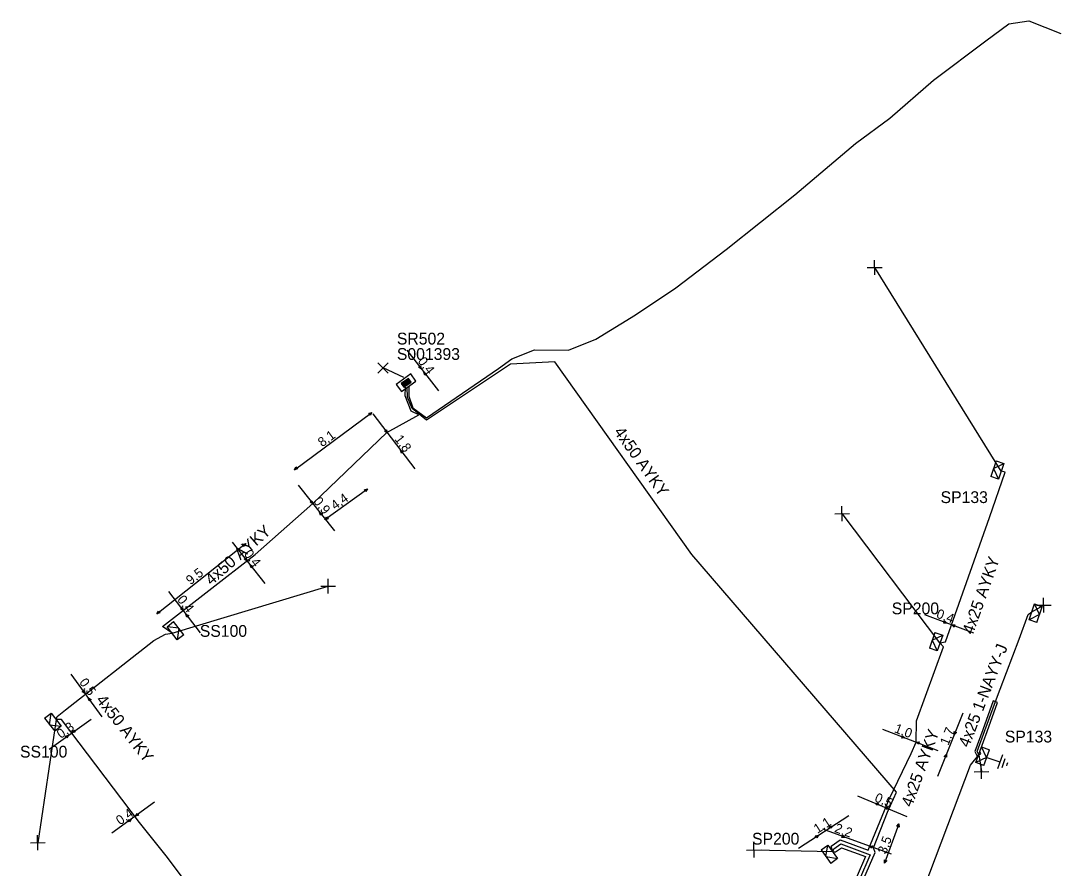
# Model space of a CAD drawing. Extents: x -762500 to -761285, y -1155006 to -1154135.
# Drawn here: x -761693.7 to -761606.3, y -1154578.8 to -1154507.3 of the extents above; entities that cross this region are included whole.
import ezdxf

# ---------------------------------------------------------------- set-up
doc = ezdxf.new("R2010")
doc.units = 0
for name, color, linetype in [('Vrstva 15', 7, 'Continuous'), ('Vrstva 20', 7, 'Continuous'), ('Vrstva 28', 7, 'Continuous'), ('Vrstva 29', 7, 'Continuous'), ('Vrstva 30', 7, 'Continuous'), ('Vrstva 31', 7, 'Continuous'), ('Vrstva 33', 7, 'Continuous'), ('Vrstva 34', 7, 'Continuous'), ('Vrstva 40', 7, 'Continuous'), ('Vrstva 5', 7, 'Continuous'), ('Vrstva 59', 7, 'Continuous'), ('Vrstva 6', 7, 'Continuous')]:
    doc.layers.add(name, color=color, linetype=linetype)

msp = doc.modelspace()

# ---------------------------------------------------------------- linework, layer by layer
at = {"layer": 'Vrstva 15'}
for points in [[(-761612.303, -1154569.415), (-761611.121, -1154569.822)], [(-761610.918, -1154569.231), (-761611.325, -1154570.412)], [(-761610.703, -1154569.559), (-761610.959, -1154570.304)], [(-761610.53, -1154570.025), (-761610.572, -1154570.146)], [(-761610.487, -1154569.899), (-761610.53, -1154570.025)]]:
    msp.add_lwpolyline(points, dxfattribs=at)
at = {"layer": 'Vrstva 20'}
msp.add_lwpolyline([(-761611.32, -1154564.8), (-761611.68, -1154564.67), (-761612.57, -1154567.12), (-761613.23, -1154568.95), (-761613.08, -1154569.29), (-761612.74, -1154569.13), (-761612.83, -1154568.93), (-761612.21, -1154567.25)], close=True, dxfattribs=at)
at = {"layer": 'Vrstva 28'}
for points in [[(-761660.844, -1154537.106), (-761662.057, -1154537.988)], [(-761660.403, -1154537.713), (-761660.844, -1154537.106)], [(-761662.057, -1154537.988), (-761661.616, -1154538.595)], [(-761661.034, -1154537.478), (-761661.636, -1154537.915)], [(-761661.636, -1154537.915), (-761661.414, -1154538.221)], [(-761661.616, -1154538.595), (-761660.403, -1154537.713)], [(-761661.044, -1154537.544), (-761661.57, -1154537.926)], [(-761661.57, -1154537.926), (-761661.403, -1154538.155)], [(-761661.055, -1154537.61), (-761661.504, -1154537.936)], [(-761661.504, -1154537.936), (-761661.393, -1154538.089)], [(-761661.065, -1154537.676), (-761661.438, -1154537.947)], [(-761661.438, -1154537.947), (-761661.382, -1154538.023)], [(-761661.414, -1154538.221), (-761660.812, -1154537.784)], [(-761661.403, -1154538.155), (-761660.878, -1154537.773)], [(-761661.393, -1154538.089), (-761660.943, -1154537.763)], [(-761661.382, -1154538.023), (-761661.009, -1154537.752)], [(-761661.071, -1154537.739), (-761661.376, -1154537.961)], [(-761661.009, -1154537.752), (-761661.065, -1154537.676)], [(-761660.943, -1154537.763), (-761661.055, -1154537.61)], [(-761660.878, -1154537.773), (-761661.044, -1154537.544)], [(-761660.812, -1154537.784), (-761661.034, -1154537.478)]]:
    msp.add_lwpolyline(points, dxfattribs=at)
at = {"layer": 'Vrstva 31'}
for points in [[(-761611.444, -1154544.418), (-761611.899, -1154545.741)], [(-761611.444, -1154544.418), (-761610.782, -1154544.645), (-761611.237, -1154545.969), (-761611.899, -1154545.741)], [(-761611.671, -1154545.079), (-761610.782, -1154544.645)], [(-761611.671, -1154545.079), (-761611.237, -1154545.969)], [(-761608.007, -1154558.053), (-761608.668, -1154557.825), (-761608.213, -1154556.501), (-761607.551, -1154556.729)], [(-761607.779, -1154557.391), (-761608.213, -1154556.501)], [(-761607.779, -1154557.391), (-761608.668, -1154557.825)], [(-761608.007, -1154558.053), (-761607.551, -1154556.729)], [(-761679.986, -1154559.092), (-761680.537, -1154559.523), (-761681.399, -1154558.42), (-761680.847, -1154557.989)], [(-761680.417, -1154558.541), (-761681.399, -1154558.42)], [(-761679.986, -1154559.092), (-761680.847, -1154557.989)], [(-761680.417, -1154558.541), (-761680.537, -1154559.523)], [(-761616.613, -1154558.897), (-761617.069, -1154560.221)], [(-761616.613, -1154558.897), (-761615.952, -1154559.125), (-761616.407, -1154560.449), (-761617.069, -1154560.221)], [(-761616.841, -1154559.559), (-761615.952, -1154559.125)], [(-761616.841, -1154559.559), (-761616.407, -1154560.449)], [(-761691.745, -1154566.127), (-761691.193, -1154565.696), (-761690.331, -1154566.799), (-761690.883, -1154567.23)], [(-761691.745, -1154566.127), (-761690.883, -1154567.23)], [(-761691.314, -1154566.679), (-761691.193, -1154565.696)], [(-761691.314, -1154566.679), (-761690.331, -1154566.799)], [(-761612.493, -1154570.11), (-761613.15, -1154569.87), (-761612.672, -1154568.555), (-761612.014, -1154568.794)], [(-761612.253, -1154569.452), (-761612.672, -1154568.555)], [(-761612.493, -1154570.11), (-761612.014, -1154568.794)], [(-761612.253, -1154569.452), (-761613.15, -1154569.87)], [(-761626.207, -1154577.226), (-761625.634, -1154576.825), (-761624.831, -1154577.972), (-761625.404, -1154578.373)], [(-761626.207, -1154577.226), (-761625.404, -1154578.373)], [(-761625.806, -1154577.8), (-761625.634, -1154576.825)], [(-761625.806, -1154577.8), (-761624.831, -1154577.972)]]:
    msp.add_lwpolyline(points, dxfattribs=at)
at = {"layer": 'Vrstva 34'}
for points in [[(-761621.679, -1154528.755), (-761621.701, -1154527.505)], [(-761622.315, -1154528.141), (-761621.065, -1154528.119)], [(-761663.622, -1154536.158), (-761662.738, -1154537.042)], [(-761663.622, -1154537.042), (-761662.738, -1154536.158)], [(-761624.429, -1154549.505), (-761624.451, -1154548.255)], [(-761625.065, -1154548.891), (-761623.815, -1154548.869)], [(-761667.799, -1154555.625), (-761667.821, -1154554.375)], [(-761668.435, -1154555.011), (-761667.185, -1154554.989)], [(-761608.045, -1154556.611), (-761606.795, -1154556.589)], [(-761607.409, -1154557.225), (-761607.431, -1154555.975)], [(-761613.305, -1154570.641), (-761612.055, -1154570.619)], [(-761612.669, -1154571.255), (-761612.691, -1154570.005)], [(-761692.935, -1154576.641), (-761691.685, -1154576.619)], [(-761692.299, -1154577.255), (-761692.321, -1154576.005)], [(-761631.869, -1154577.875), (-761631.891, -1154576.625)], [(-761632.505, -1154577.261), (-761631.255, -1154577.239)]]:
    msp.add_lwpolyline(points, dxfattribs=at)
at = {"layer": 'Vrstva 40'}
for points in [[(-761661.18, -1154535.09), (-761658.51, -1154538.54)], [(-761670.66, -1154545.18), (-761664.12, -1154540.35)], [(-761664.04, -1154540.47), (-761660.48, -1154545.11)], [(-761670.35, -1154546.49), (-761667.28, -1154550.32)], [(-761668.08, -1154549.39), (-761664.49, -1154546.79)], [(-761682.26, -1154557.33), (-761674.77, -1154551.41)], [(-761675.9, -1154551.29), (-761673.15, -1154554.77)], [(-761678.59, -1154558.94), (-761681.26, -1154555.46)], [(-761613.31, -1154558.96), (-761617.47, -1154557.41)], [(-761686.87, -1154566.03), (-761689.5, -1154562.42)], [(-761691.34, -1154568.73), (-761687.8, -1154566.21)], [(-761616.37, -1154571.01), (-761614.23, -1154565.68)], [(-761616.33, -1154568.87), (-761621.01, -1154567.08)], [(-761682.45, -1154573.22), (-761686.05, -1154575.83)], [(-761623.14, -1154572.67), (-761618.99, -1154574.43)], [(-761628.12, -1154577.08), (-761623.88, -1154574.33)], [(-761619.65, -1154575.04), (-761620.85, -1154578.35)], [(-761620.27, -1154577.61), (-761626.07, -1154575.5)]]:
    msp.add_lwpolyline(points, dxfattribs=at)
for points in [[(-761659.948, -1154536.672), (-761660.184, -1154536.541), (-761660.019, -1154536.412)], [(-761659.732, -1154536.958), (-761659.496, -1154537.09), (-761659.661, -1154537.218)], [(-761664.118, -1154540.349), (-761664.253, -1154540.582), (-761664.379, -1154540.415)], [(-761662.819, -1154542.062), (-761663.054, -1154541.931), (-761662.889, -1154541.802)], [(-761661.701, -1154543.518), (-761661.466, -1154543.649), (-761661.631, -1154543.778)], [(-761670.662, -1154545.181), (-761670.526, -1154544.948), (-761670.401, -1154545.115)], [(-761664.488, -1154546.788), (-761664.628, -1154547.019), (-761664.751, -1154546.85)], [(-761669.099, -1154548.052), (-761669.336, -1154547.925), (-761669.174, -1154547.793)], [(-761668.531, -1154548.758), (-761668.294, -1154548.885), (-761668.456, -1154549.017)], [(-761668.082, -1154549.391), (-761667.942, -1154549.161), (-761667.82, -1154549.33)], [(-761674.768, -1154551.408), (-761674.895, -1154551.646), (-761675.027, -1154551.483)], [(-761674.659, -1154552.862), (-761674.896, -1154552.735), (-761674.734, -1154552.603)], [(-761674.391, -1154553.198), (-761674.154, -1154553.325), (-761674.316, -1154553.457)], [(-761682.262, -1154557.331), (-761682.135, -1154557.093), (-761682.003, -1154557.256)], [(-761680.039, -1154557.052), (-761680.274, -1154556.921), (-761680.109, -1154556.792)], [(-761679.811, -1154557.348), (-761679.576, -1154557.479), (-761679.741, -1154557.608)], [(-761615.598, -1154558.111), (-761615.867, -1154558.125), (-761615.796, -1154557.928)], [(-761615.192, -1154558.259), (-761614.923, -1154558.246), (-761614.994, -1154558.443)], [(-761688.319, -1154564.042), (-761688.552, -1154563.907), (-761688.385, -1154563.781)], [(-761688.051, -1154564.408), (-761687.818, -1154564.544), (-761687.985, -1154564.669)], [(-761689.432, -1154567.371), (-761689.293, -1154567.141), (-761689.17, -1154567.31)], [(-761689.708, -1154567.569), (-761689.847, -1154567.799), (-761689.97, -1154567.63)], [(-761619.138, -1154567.791), (-761619.407, -1154567.804), (-761619.336, -1154567.608)], [(-761614.981, -1154567.533), (-761614.99, -1154567.263), (-761614.794, -1154567.338)], [(-761618.202, -1154568.149), (-761617.933, -1154568.136), (-761618.004, -1154568.332)], [(-761615.629, -1154569.158), (-761615.62, -1154569.428), (-761615.815, -1154569.353)], [(-761621.298, -1154573.451), (-761621.567, -1154573.45), (-761621.486, -1154573.258)], [(-761684.073, -1154574.392), (-761683.933, -1154574.161), (-761683.81, -1154574.33)], [(-761620.832, -1154573.649), (-761620.563, -1154573.65), (-761620.644, -1154573.842)], [(-761684.428, -1154574.649), (-761684.568, -1154574.88), (-761684.691, -1154574.711)], [(-761619.649, -1154575.038), (-761619.632, -1154575.307), (-761619.829, -1154575.239)], [(-761625.562, -1154575.421), (-761625.414, -1154575.195), (-761625.297, -1154575.369)], [(-761626.438, -1154575.989), (-761626.585, -1154576.215), (-761626.702, -1154576.042)], [(-761624.188, -1154576.181), (-761624.457, -1154576.199), (-761624.389, -1154576.001)], [(-761622.152, -1154576.919), (-761621.883, -1154576.901), (-761621.951, -1154577.099)], [(-761620.851, -1154578.353), (-761620.869, -1154578.083), (-761620.672, -1154578.151)]]:
    msp.add_lwpolyline(points, close=True, dxfattribs=at)
at = {"layer": 'Vrstva 5'}
for points in [[(-761661.01, -1154538.15), (-761660.99, -1154538.97), (-761660.65, -1154539.96), (-761659.51, -1154540.79), (-761653.43, -1154536.64), (-761652.32, -1154535.82), (-761650.39, -1154535.07), (-761647.54, -1154535.11), (-761645.23, -1154534.16), (-761641.87, -1154532.12), (-761638.47, -1154529.84), (-761634.23, -1154526.62), (-761628.42, -1154521.99), (-761623.3, -1154517.67), (-761620.4, -1154515.53), (-761616.72, -1154512.32), (-761612.32, -1154509), (-761610.36, -1154507.57), (-761608.67, -1154507.32), (-761605.97, -1154508.4)], [(-761622.04, -1154593.03), (-761622.16, -1154592.65), (-761626.67, -1154590.74), (-761622.6, -1154579.64), (-761621.66, -1154577.46), (-761621.79, -1154577.06), (-761620.62, -1154574.05), (-761619.85, -1154572.37), (-761637.13, -1154552.32), (-761648.69, -1154536.07), (-761652.41, -1154536.27), (-761659.5, -1154540.99), (-761660.72, -1154540.01), (-761661.12, -1154539.06), (-761661.14, -1154538.24)], [(-761675.5, -1154585.7), (-761681.49, -1154577.75), (-761683.72, -1154574.92), (-761690.32, -1154566.25), (-761690.76, -1154566.25), (-761690.67, -1154565.99), (-761689.96, -1154565.42), (-761682.51, -1154559.57), (-761681.53, -1154559.04), (-761680.97, -1154558.97), (-761681.79, -1154558.4), (-761673.98, -1154552.32), (-761669.1, -1154548.04), (-761662.87, -1154542.04), (-761660.16, -1154540.56), (-761660.81, -1154540.25), (-761661.32, -1154538.96), (-761661.29, -1154538.23)], [(-761616.18, -1154559.79), (-761615.72, -1154559.7), (-761612.01, -1154549.21), (-761610.67, -1154545.39), (-761611.01, -1154545.31)], [(-761612.91, -1154569.21), (-761613.03, -1154568.94), (-761612.39, -1154567.18), (-761611.5, -1154564.73), (-761611.11, -1154563.67), (-761609.49, -1154559.48), (-761608.74, -1154557.38), (-761608.44, -1154557.16)], [(-761625.23, -1154577.4), (-761625.36, -1154576.93), (-761624.59, -1154576.38), (-761622.24, -1154577.26), (-761620.48, -1154572.96), (-761618.62, -1154569.12), (-761618.2, -1154568.15), (-761618.16, -1154566.36), (-761615.88, -1154560.1), (-761616.18, -1154559.79)], [(-761621.99, -1154592.91), (-761621.89, -1154592.03), (-761613.6, -1154570.1), (-761612.91, -1154569.21)], [(-761625.23, -1154577.4), (-761625.15, -1154577.15), (-761624.54, -1154576.72), (-761622.06, -1154577.64), (-761622.18, -1154577.91), (-761622.88, -1154579.53), (-761625.16, -1154586.19), (-761627.06, -1154590.9), (-761622.47, -1154592.8), (-761622.09, -1154593.15)], [(-761625.23, -1154577.4), (-761624.99, -1154577.39), (-761624.5, -1154577.05), (-761622.46, -1154577.79), (-761623.16, -1154579.42), (-761625.44, -1154586.08), (-761627.34, -1154590.79), (-761629.49, -1154594.07), (-761630.52, -1154595.68), (-761634.83, -1154602.56), (-761636.8, -1154604.93), (-761639.28, -1154606.99), (-761645.39, -1154610.82), (-761648.2, -1154611.18), (-761650.88, -1154609.13), (-761652.37, -1154607.42), (-761653.76, -1154605.77), (-761656.21, -1154602.49), (-761657.87, -1154600.45), (-761657.72, -1154600.17)]]:
    msp.add_lwpolyline(points, dxfattribs=at)
at = {"layer": 'Vrstva 59'}
for points in [[(-761611.01, -1154545.31), (-761621.69, -1154528.13)], [(-761661.41, -1154537.41), (-761663.18, -1154536.6)], [(-761616.18, -1154559.79), (-761624.44, -1154548.88)], [(-761680.97, -1154558.97), (-761667.81, -1154555)], [(-761608.44, -1154557.16), (-761607.42, -1154556.6)], [(-761690.76, -1154566.25), (-761692.31, -1154576.63)], [(-761612.91, -1154569.21), (-761612.68, -1154570.63)], [(-761625.23, -1154577.4), (-761631.88, -1154577.25)]]:
    msp.add_lwpolyline(points, dxfattribs=at)

# ---------------------------------------------------------------- texts
at = {"layer": 'Vrstva 29'}
msp.add_text('S001393', height=0.9943, dxfattribs=at).set_placement((-761662.01, -1154535.92))
at = {"layer": 'Vrstva 30'}
msp.add_text('SR502', height=0.9943, dxfattribs=at).set_placement((-761662.01, -1154534.62))
at = {"layer": 'Vrstva 33'}
for s, p in [('SP133', (-761616.13, -1154547.99)), ('SP200', (-761620.25, -1154557.37)), ('SS100', (-761678.64, -1154559.27)), ('SP133', (-761610.71, -1154568.18)), ('SS100', (-761693.81, -1154569.45)), ('SP200', (-761632.04, -1154576.79))]:
    msp.add_text(s, height=0.9943, dxfattribs=at).set_placement(p)
at = {"layer": 'Vrstva 40'}
for s, rotation, p in [('0,4', 307.71611, (-761660.29, -1154536.04)), ('8,1', 36.42471, (-761668.31, -1154543.3)), ('1,8', 307.494, (-761662.25, -1154542.61)), ('0,9', 308.75972, (-761669.1, -1154547.86)), ('4,4', 35.93145, (-761667.22, -1154548.61)), ('0,4', 308.45812, (-761674.96, -1154552.3)), ('9,5', 38.32234, (-761679.42, -1154554.93)), ('0,4', 307.4725, (-761680.59, -1154556.14)), ('0,4', 339.51546, (-761616.55, -1154557.63)), ('0,5', 306.12018, (-761688.85, -1154563.11)), ('0,3', 35.54064, (-761690.36, -1154567.89)), ('1,0', 339.04621, (-761620.09, -1154567.3)), ('1,7', 68.11944, (-761615.48, -1154568.48)), ('0,5', 336.9534, (-761621.76, -1154573.12)), ('0,4', 35.83232, (-761685.36, -1154575.18)), ('1,1', 33.00609, (-761626.52, -1154575.89)), ('2,2', 340.06242, (-761625.14, -1154575.71)), ('3,5', 70.07195, (-761620.73, -1154577.65))]:
    msp.add_text(s, height=0.7954, rotation=rotation, dxfattribs=at).set_placement(p)
at = {"layer": 'Vrstva 6'}
for s, height, rotation, p in [('4x50 AYKY', 0.9943, 305.41909, (-761643.74, -1154541.99)), ('4x50 AYKY', 0.9943, 41.25236, (-761677.66, -1154554.98)), ('4x25 AYKY', 0.9943, 70.51283, (-761613.4, -1154559.14)), ('4x25 1-NAYY-J', 0.99429, 68.86176, (-761613.74, -1154568.66)), ('4x50 AYKY', 0.9943, 308.14024, (-761687.45, -1154564.62)), ('4x25 AYKY', 0.9943, 69.95148, (-761618.56, -1154573.69))]:
    msp.add_text(s, height=height, rotation=rotation, dxfattribs=at).set_placement(p)

doc.saveas('drawing.dxf')
